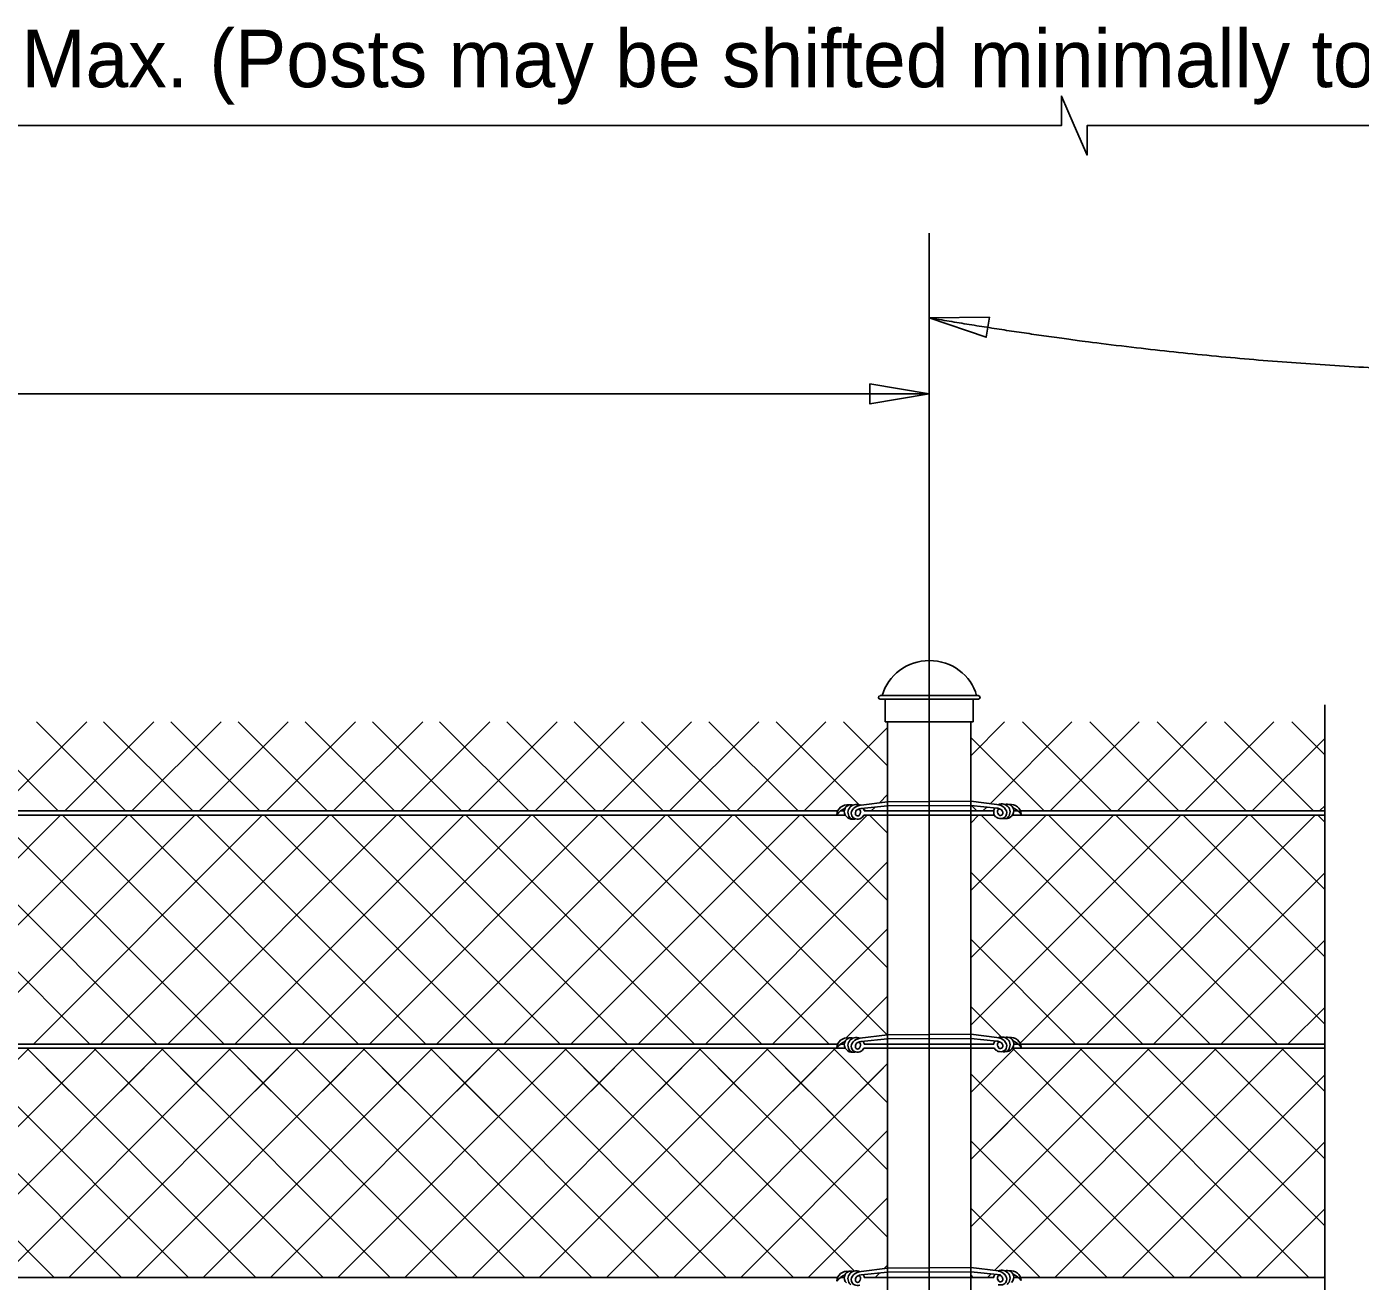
# Model space of a CAD drawing. Extents: x 0 to 41, y -96 to 25.
# Drawn here: x 12.158 to 16.836, y 20.556 to 24.956 of the extents above; entities that cross this region are included whole.
import ezdxf

# ---------------------------------------------------------------- set-up
doc = ezdxf.new("R2010")
doc.units = 0
for name, color, linetype in [('CL_Major', 7, 'Continuous'), ('Dimension', 7, 'Continuous'), ('Miscellaneous', 7, 'Continuous'), ('SteelMisc', 7, 'Continuous'), ('SteelMisc_h', 7, 'Continuous'), ('TextStructures', 7, 'Continuous')]:
    doc.layers.add(name, color=color, linetype=linetype)

msp = doc.modelspace()

# ---------------------------------------------------------------- linework, layer by layer
at = {"layer": 'CL_Major'}
msp.add_line((15.3237, 24.2317), (15.3237, 12.9956), dxfattribs=at)
at = {"layer": 'Dimension'}
for p, q in [((0.9439, 24.6092), (14.3237, 24.6092)), ((5.3237, 23.6682), (15.3237, 23.6682))]:
    msp.add_line(p, q, dxfattribs=at)
for points in [[(14.3237, 24.6092), (15.7874, 24.6092), (15.7874, 24.7126), (15.8324, 24.6092), (15.8774, 24.5059), (15.8774, 24.6092), (29.1682, 24.6092)], [(16.7107, 22.5773), (16.7107, 19.3509), (16.814, 19.3509), (16.7107, 19.3059), (16.6074, 19.2609), (16.7107, 19.2609), (16.7107, 18.3673)]]:
    msp.add_lwpolyline(points, dxfattribs=at)
for points in [[(15.3237, 23.9351), (15.5237, 23.8671), (15.5349, 23.9368)], [(15.3237, 23.6682), (15.1155, 23.7035), (15.1155, 23.6329)]]:
    msp.add_lwpolyline(points, close=True, dxfattribs=at)
msp.add_open_spline([(19.3053, 23.7363), (18.502, 23.7363), (17.1126, 23.7363), (15.9312, 23.8309), (15.3237, 23.935)], degree=2, dxfattribs=at)
at = {"layer": 'Miscellaneous'}
for p, q in [((11.9568, 22.5181), (12.2693, 22.2055)), ((12.0562, 22.2055), (12.3688, 22.5181)), ((12.1925, 22.5181), (12.505, 22.2055)), ((12.2919, 22.2055), (12.6045, 22.5181)), ((12.4282, 22.5181), (12.7407, 22.2055)), ((12.5276, 22.2055), (12.8402, 22.5181)), ((12.6639, 22.5181), (12.9765, 22.2055)), ((12.7634, 22.2055), (13.0759, 22.5181)), ((12.8996, 22.5181), (13.2122, 22.2055)), ((12.9991, 22.2055), (13.3116, 22.5181)), ((13.1353, 22.5181), (13.4479, 22.2055)), ((13.2348, 22.2055), (13.5473, 22.5181)), ((13.371, 22.5181), (13.6836, 22.2055)), ((13.4705, 22.2055), (13.783, 22.5181)), ((13.6067, 22.5181), (13.9193, 22.2055)), ((13.7062, 22.2055), (14.0187, 22.5181)), ((13.8424, 22.5181), (14.155, 22.2055)), ((13.9419, 22.2055), (14.2544, 22.5181)), ((14.0786, 22.5181), (14.3911, 22.2055)), ((14.1776, 22.2055), (14.4901, 22.5181)), ((14.3148, 22.5181), (14.6273, 22.2055)), ((14.4133, 22.2055), (14.7258, 22.5181)), ((14.5509, 22.5181), (14.8635, 22.2055)), ((14.649, 22.2055), (14.9615, 22.5181)), ((14.7871, 22.5181), (15.0782, 22.227)), ((14.8847, 22.2055), (15.1779, 22.4988)), ((15.0233, 22.5181), (15.1779, 22.3635)), ((15.4696, 22.3994), (15.5882, 22.5181)), ((15.5376, 22.2312), (15.8244, 22.5181)), ((15.651, 22.5181), (15.9635, 22.2055)), ((15.748, 22.2055), (16.0606, 22.5181)), ((15.8871, 22.5181), (16.1997, 22.2055)), ((15.9842, 22.2055), (16.2967, 22.5181)), ((16.1233, 22.5181), (16.4358, 22.2055)), ((16.2204, 22.2055), (16.5329, 22.5181)), ((16.3595, 22.5181), (16.672, 22.2055)), ((16.5957, 22.5181), (16.7107, 22.403)), ((15.4696, 22.4633), (15.7273, 22.2055)), ((16.4566, 22.2055), (16.7107, 22.4597)), ((15.1204, 22.2055), (15.1339, 22.2191)), ((15.1494, 22.2346), (15.1779, 22.2631)), ((15.4717, 22.225), (15.4911, 22.2055)), ((15.5119, 22.2055), (15.5257, 22.2194)), ((16.6923, 22.2055), (16.7107, 22.224)), ((11.4745, 21.3881), (12.2772, 22.1908)), ((11.577, 22.1908), (12.3796, 21.3881)), ((11.7103, 21.3881), (12.5129, 22.1908)), ((11.8127, 22.1908), (12.6153, 21.3881)), ((11.946, 21.3881), (12.7486, 22.1908)), ((12.0484, 22.1908), (12.851, 21.3881)), ((12.1817, 21.3881), (12.9843, 22.1908)), ((12.2841, 22.1908), (13.0867, 21.3881)), ((12.4174, 21.3881), (13.22, 22.1908)), ((12.5198, 22.1908), (13.3224, 21.3881)), ((12.6531, 21.3881), (13.4557, 22.1908)), ((12.7555, 22.1908), (13.5581, 21.3881)), ((12.8888, 21.3881), (13.6914, 22.1908)), ((12.9912, 22.1908), (13.7938, 21.3881)), ((13.1245, 21.3881), (13.9271, 22.1908)), ((13.2269, 22.1908), (14.0296, 21.3881)), ((13.3602, 21.3881), (14.1628, 22.1908)), ((13.4626, 22.1908), (14.2653, 21.3881)), ((13.5959, 21.3881), (14.3985, 22.1908)), ((13.6983, 22.1908), (14.501, 21.3881)), ((13.8316, 21.3881), (14.6342, 22.1908)), ((13.934, 22.1908), (14.7367, 21.3881)), ((14.0673, 21.3881), (14.8699, 22.1908)), ((14.1697, 22.1908), (14.9724, 21.3881)), ((14.303, 21.3881), (15.1056, 22.1908)), ((14.4059, 22.1908), (15.1762, 21.4205)), ((14.6421, 22.1908), (15.1779, 21.6549)), ((14.8782, 22.1908), (15.1779, 21.8911)), ((15.0931, 22.2121), (15.0997, 22.2055)), ((15.1144, 22.1908), (15.1779, 22.1273)), ((15.4696, 21.4547), (16.2056, 22.1908)), ((15.4696, 21.6909), (15.9695, 22.1908)), ((15.4696, 21.9271), (15.7333, 22.1908)), ((15.4696, 22.1633), (15.4971, 22.1908)), ((15.5059, 22.1908), (16.3085, 21.3881)), ((15.6425, 21.3915), (16.4418, 22.1908)), ((15.7421, 22.1908), (16.5447, 21.3881)), ((15.8749, 21.3881), (16.6775, 22.1908)), ((15.9782, 22.1908), (16.7107, 21.4583)), ((16.2144, 22.1908), (16.7107, 21.6945)), ((16.4506, 22.1908), (16.7107, 21.9307)), ((16.6868, 22.1908), (16.7107, 22.1669)), ((14.5387, 21.3881), (15.1779, 22.0274)), ((15.4696, 21.9914), (16.0728, 21.3881)), ((16.1106, 21.3881), (16.7107, 21.9883)), ((14.7744, 21.3881), (15.1779, 21.7917)), ((15.4696, 21.7557), (15.8371, 21.3881)), ((16.3463, 21.3881), (16.7107, 21.7526)), ((15.0311, 21.4092), (15.1779, 21.556)), ((15.4696, 21.52), (15.5766, 21.413)), ((16.582, 21.3881), (16.7107, 21.5169)), ((11.3635, 20.57), (12.1669, 21.3734)), ((11.4516, 21.3734), (12.255, 20.57)), ((11.5992, 20.57), (12.4026, 21.3734)), ((11.6873, 21.3734), (12.4907, 20.57)), ((11.8349, 20.57), (12.6383, 21.3734)), ((11.923, 21.3734), (12.7264, 20.57)), ((12.0706, 20.57), (12.874, 21.3734)), ((12.1587, 21.3734), (12.9621, 20.57)), ((12.3063, 20.57), (13.1097, 21.3734)), ((12.3944, 21.3734), (13.1978, 20.57)), ((12.542, 20.57), (13.3454, 21.3734)), ((12.6301, 21.3734), (13.4335, 20.57)), ((12.7777, 20.57), (13.5811, 21.3734)), ((12.8658, 21.3734), (13.6692, 20.57)), ((13.0134, 20.57), (13.8168, 21.3734)), ((13.1015, 21.3734), (13.9049, 20.57)), ((13.2491, 20.57), (14.0525, 21.3734)), ((13.3372, 21.3734), (14.1406, 20.57)), ((13.4848, 20.57), (14.2882, 21.3734)), ((13.5729, 21.3734), (14.3763, 20.57)), ((13.7205, 20.57), (14.5239, 21.3734)), ((13.8086, 21.3734), (14.612, 20.57)), ((13.9562, 20.57), (14.7596, 21.3734)), ((14.0443, 21.3734), (14.8477, 20.57)), ((14.1919, 20.57), (14.9953, 21.3734)), ((14.28, 21.3734), (15.0612, 20.5922)), ((14.5157, 21.3734), (15.1779, 20.7112)), ((14.7514, 21.3734), (15.1779, 20.9469)), ((14.9871, 21.3734), (15.1779, 21.1826)), ((15.4696, 21.2186), (15.6244, 21.3734)), ((15.4696, 20.7472), (16.0958, 21.3734)), ((15.4696, 20.9829), (15.8601, 21.3734)), ((15.5526, 20.5944), (16.3315, 21.3734)), ((15.6162, 21.3734), (16.4196, 20.57)), ((15.7638, 20.57), (16.5672, 21.3734)), ((15.8519, 21.3734), (16.6553, 20.57)), ((16.0876, 21.3734), (16.7107, 20.7503)), ((16.3233, 21.3734), (16.7107, 20.986)), ((16.5595, 21.3734), (16.7107, 21.2222)), ((12.1677, 21.1385), (12.3344, 21.3051)), ((12.2269, 21.3051), (12.3936, 21.1385)), ((12.4034, 21.1385), (12.5701, 21.3051)), ((12.4626, 21.3051), (12.6293, 21.1385)), ((12.6391, 21.1385), (12.8058, 21.3051)), ((12.6983, 21.3051), (12.865, 21.1385)), ((12.8748, 21.1385), (13.0415, 21.3051)), ((12.934, 21.3051), (13.1007, 21.1385)), ((13.1105, 21.1385), (13.2772, 21.3051)), ((13.1697, 21.3051), (13.3364, 21.1385)), ((13.3462, 21.1385), (13.5129, 21.3051)), ((13.4054, 21.3051), (13.5721, 21.1385)), ((13.5819, 21.1385), (13.7486, 21.3051)), ((13.6411, 21.3051), (13.8078, 21.1385)), ((13.8176, 21.1385), (13.9843, 21.3051)), ((13.8768, 21.3051), (14.0435, 21.1385)), ((14.0533, 21.1385), (14.22, 21.3051)), ((14.1125, 21.3051), (14.2792, 21.1385)), ((14.289, 21.1385), (14.4557, 21.3051)), ((14.3482, 21.3051), (14.5149, 21.1385)), ((14.4276, 20.57), (15.1779, 21.3203)), ((14.5247, 21.1385), (14.6914, 21.3051)), ((14.5839, 21.3051), (14.7506, 21.1385)), ((14.7604, 21.1385), (14.9271, 21.3051)), ((14.8196, 21.3051), (14.9863, 21.1385)), ((14.9961, 21.1385), (15.1628, 21.3051)), ((15.4696, 21.2843), (16.1839, 20.57)), ((16, 20.57), (16.7107, 21.2807)), ((15.4696, 20.9829), (15.5991, 21.1123)), ((14.6633, 20.57), (15.1779, 21.0846)), ((15.4696, 21.0486), (15.9482, 20.57)), ((16.2352, 20.57), (16.7107, 21.0454)), ((14.899, 20.57), (15.1779, 20.8489)), ((15.4696, 20.8129), (15.7125, 20.57)), ((16.4709, 20.57), (16.7107, 20.8097)), ((15.1347, 20.57), (15.1499, 20.5851)), ((15.1658, 20.601), (15.1779, 20.6132)), ((15.5281, 20.57), (15.5406, 20.5824)), ((15.4696, 20.5772), (15.4768, 20.57)), ((16.7066, 20.57), (16.7107, 20.574))]:
    msp.add_line(p, q, dxfattribs=at)
at = {"layer": 'SteelMisc'}
for p, q in [((15.1514, 22.6101), (15.496, 22.6101)), ((15.496, 22.5978), (15.1514, 22.5978)), ((15.1697, 22.5181), (15.1697, 22.5978)), ((15.4778, 22.5181), (15.4778, 22.5978)), ((15.4778, 22.5181), (15.1697, 22.5181)), ((15.1779, 16.0337), (15.1779, 22.5181)), ((15.4696, 16.0337), (15.4696, 22.5181)), ((15.1779, 22.2381), (15.0851, 22.2265)), ((15.1779, 22.2236), (15.0851, 22.214)), ((15.1779, 22.2381), (15.4691, 22.2398)), ((15.1779, 22.2236), (15.4691, 22.2253)), ((15.4691, 22.2398), (15.561, 22.2283)), ((15.4691, 22.2253), (15.561, 22.2158)), ((5.6284, 22.2055), (15.0028, 22.2055)), ((5.6317, 22.1908), (15.0294, 22.1908)), ((15.0127, 22.2055), (15.0259, 22.2055)), ((15.0943, 22.1908), (15.1779, 22.1908)), ((15.0958, 22.2055), (15.1779, 22.2055)), ((15.4696, 22.2055), (15.55, 22.2055)), ((15.4696, 22.1908), (15.5527, 22.1908)), ((15.6154, 22.1908), (16.7107, 22.1908)), ((15.6204, 22.2055), (15.6356, 22.2055)), ((15.6441, 22.2055), (16.7107, 22.2055)), ((5.6284, 21.3881), (15.0028, 21.3881)), ((15.0127, 21.3881), (15.0259, 21.3881)), ((15.1779, 21.4207), (15.0808, 21.4086)), ((15.1779, 21.4062), (15.0851, 21.3966)), ((15.0958, 21.3881), (15.1779, 21.3881)), ((15.1779, 21.4207), (15.4691, 21.4224)), ((15.1779, 21.4062), (15.4691, 21.4079)), ((15.4691, 21.4224), (15.561, 21.4109)), ((15.4691, 21.4079), (15.561, 21.3984)), ((15.4696, 21.3881), (15.55, 21.3881)), ((15.6204, 21.3881), (15.6356, 21.3881)), ((15.6441, 21.3881), (16.7107, 21.3881)), ((5.6317, 21.3734), (15.0294, 21.3734)), ((15.0943, 21.3734), (15.1779, 21.3734)), ((15.4696, 21.3734), (15.5527, 21.3734)), ((15.6154, 21.3734), (16.7107, 21.3734)), ((15.1779, 20.6026), (15.0851, 20.5909)), ((15.1779, 20.5881), (15.0851, 20.5784)), ((15.1779, 20.6026), (15.4691, 20.6043)), ((15.1779, 20.5881), (15.4691, 20.5897)), ((15.4691, 20.6043), (15.5668, 20.5927)), ((15.4691, 20.5897), (15.5738, 20.5791)), ((5.6284, 20.57), (15.0028, 20.57)), ((15.0127, 20.57), (15.0259, 20.57)), ((15.0958, 20.57), (15.1779, 20.57)), ((15.4696, 20.57), (15.55, 20.57)), ((15.6204, 20.57), (15.6356, 20.57)), ((15.6441, 20.57), (16.7107, 20.57))]:
    msp.add_line(p, q, dxfattribs=at)
for centre, start, end in [((15.1516, 22.6038), 91.1647, 268.8353), ((15.4959, 22.6038), 271.1647, 88.8353)]:
    msp.add_arc(centre, 0.00613, start, end, dxfattribs=at)
for centre, major_axis, ratio, start_param, end_param in [((15.3244, 22.569), (0.1711, 0), 0.957868, 0.252602, 2.888574), ((15.037, 22.1913), (0.0373, 0), 0.957868, 1.427863, 3.108042), ((15.0495, 22.2057), (0.023, 0), 0.957868, 1.234085, 2.861055), ((15.0683, 22.2004), (0.0295, 0), 0.957868, 1.132635, 3.996184), ((15.0817, 22.2022), (-0.0303, -0.0108), 0.724765, 4.35367, 6.224248), ((15.5644, 22.2039), (0.0303, -0.0108), 0.724765, 0.058937, 1.929515), ((15.5778, 22.2021), (-0.0295, 0), 0.957868, 2.287002, 5.15055), ((15.5966, 22.2075), (-0.023, 0), 0.957868, 3.422131, 5.0491), ((15.6091, 22.193), (-0.0373, 0), 0.957868, 3.175144, 4.855322), ((15.0581, 22.1516), (-0.0724, 0), 0.957868, 5.133134, 5.652106), ((15.0507, 22.2032), (-0.0249, 0), 0.957868, 5.913851, 7.104804), ((15.052, 22.1992), (0.0231, 0), 0.957868, 3.795406, 4.839145), ((15.0581, 22.1935), (0.0206, -0.0021), 0.798607, 4.32653, 5.170153), ((15.0716, 22.1935), (0.0206, -0.0021), 0.798607, 3.319436, 5.220153), ((15.0784, 22.1981), (-0.0139, 0), 0.957868, 5.075258, 6.485782), ((15.0728, 22.1957), (-0.00795, 0), 0.957868, 0.039428, 2.999692), ((15.0868, 22.1892), (-0.0259, 0), 0.957868, 4.777514, 5.251802), ((15.0711, 22.2015), (0.0119, 0), 0.957868, 5.725876, 7.416677), ((15.0642, 22.2123), (0.0391, 0), 0.957868, 5.134108, 5.41974), ((15.0711, 22.2015), (0.0119, 0), 0.957868, 5.639684, 5.725876), ((15.0713, 22.2003), (0.0251, 0), 0.957868, 5.531357, 5.877802), ((15.0713, 22.2003), (0.0251, 0), 0.957868, 0.221743, 0.642584), ((15.5748, 22.202), (-0.0251, 0), 0.957868, 6.136824, 7.035014), ((15.5748, 22.202), (-0.0251, 0), 0.957868, 5.640694, 6.136824), ((15.5819, 22.2141), (-0.0391, 0), 0.957868, 0.863445, 1.149078), ((15.5593, 22.191), (0.0259, 0), 0.957868, 1.031384, 1.505671), ((15.575, 22.2033), (-0.0119, 0), 0.957868, 5.149694, 6.840495), ((15.575, 22.2033), (-0.0119, 0), 0.957868, 0.560069, 0.643501), ((15.5734, 22.1975), (0.00795, 0), 0.957868, 3.283494, 6.243757), ((15.5745, 22.1953), (-0.0206, -0.0021), 0.798607, 1.063032, 2.96375), ((15.5677, 22.1999), (0.0139, 0), 0.957868, 6.080589, 7.491112), ((15.588, 22.1953), (-0.0206, -0.0021), 0.798607, 1.113032, 1.956656), ((15.5941, 22.201), (-0.0231, 0), 0.957868, 1.44404, 2.487779), ((15.5955, 22.205), (0.0249, 0), 0.957868, 5.461566, 6.65252), ((15.588, 22.1533), (0.0724, 0), 0.957868, 0.631079, 1.150052), ((15.037, 21.3739), (0.0373, 0), 0.957868, 1.427863, 3.108042), ((15.0581, 21.3342), (-0.0724, 0), 0.957868, 5.133134, 5.652106), ((15.0507, 21.3858), (-0.0249, 0), 0.957868, 5.913851, 7.089857), ((15.0495, 21.3883), (0.023, 0), 0.957868, 1.234085, 2.861055), ((15.0683, 21.383), (0.0295, 0), 0.957868, 1.132635, 3.996184), ((15.0817, 21.3848), (-0.0303, -0.0108), 0.724765, 4.490702, 6.224248), ((15.0784, 21.3807), (-0.0139, 0), 0.957868, 5.075258, 6.485782), ((15.0728, 21.3783), (-0.00795, 0), 0.957868, 0.039428, 2.999692), ((15.0868, 21.3718), (-0.0259, 0), 0.957868, 4.777514, 5.251802), ((15.0711, 21.3841), (0.0119, 0), 0.957868, 5.725876, 7.416677), ((15.0711, 21.3841), (0.0119, 0), 0.957868, 5.639684, 5.725876), ((15.0713, 21.3829), (0.0251, 0), 0.957868, 0.221743, 0.642584), ((15.5748, 21.3846), (-0.0251, 0), 0.957868, 5.640694, 6.136824), ((15.5644, 21.3865), (0.0303, -0.0108), 0.724765, 0.058937, 1.929515), ((15.5593, 21.3736), (0.0259, 0), 0.957868, 1.031384, 1.505671), ((15.575, 21.3859), (-0.0119, 0), 0.957868, 5.149694, 6.840495), ((15.575, 21.3859), (-0.0119, 0), 0.957868, 0.560069, 0.643501), ((15.5778, 21.3847), (-0.0295, 0), 0.957868, 2.287002, 5.15055), ((15.5734, 21.3801), (0.00795, 0), 0.957868, 3.283494, 6.243757), ((15.5745, 21.3779), (-0.0206, -0.0021), 0.798607, 1.063032, 2.96375), ((15.5677, 21.3825), (0.0139, 0), 0.957868, 6.080589, 7.491112), ((15.5966, 21.3901), (-0.023, 0), 0.957868, 3.422131, 5.0491), ((15.6091, 21.3756), (-0.0373, 0), 0.957868, 3.175144, 4.855322), ((15.5955, 21.3876), (0.0249, 0), 0.957868, 5.476514, 6.65252), ((15.588, 21.3359), (0.0724, 0), 0.957868, 0.631079, 1.150052), ((15.052, 21.3818), (0.0231, 0), 0.957868, 3.779554, 4.839145), ((15.0581, 21.3761), (0.0206, -0.0021), 0.798607, 4.32653, 5.170153), ((15.0716, 21.3761), (0.0206, -0.0021), 0.798607, 3.319436, 5.220153), ((15.0642, 21.3949), (0.0391, 0), 0.957868, 5.134108, 5.41974), ((15.0713, 21.3829), (0.0251, 0), 0.957868, 5.531357, 5.877802), ((15.5748, 21.3846), (-0.0251, 0), 0.957868, 0.487549, 0.751829), ((15.5819, 21.3967), (-0.0391, 0), 0.957868, 0.863445, 1.149078), ((15.588, 21.3779), (-0.0206, -0.0021), 0.798607, 1.113032, 1.956656), ((15.5941, 21.3836), (-0.0231, 0), 0.957868, 1.44404, 2.503632), ((15.037, 20.5557), (0.0373, 0), 0.957868, 1.427863, 3.108042), ((15.0495, 20.5702), (0.023, 0), 0.957868, 1.234085, 2.861055), ((15.0683, 20.5648), (0.0295, 0), 0.957868, 1.132635, 3.996184), ((15.0817, 20.5666), (-0.0303, -0.0108), 0.724765, 4.35367, 6.224248), ((15.5748, 20.5665), (-0.0251, 0), 0.957868, 5.633507, 6.136824), ((15.5778, 20.5666), (-0.0295, 0), 0.957868, 2.287002, 5.15055), ((15.5644, 20.5684), (0.0303, -0.0108), 0.724765, 0.058937, 1.792483), ((15.5966, 20.5719), (-0.023, 0), 0.957868, 3.422131, 5.0491), ((15.6091, 20.5575), (-0.0373, 0), 0.957868, 3.175144, 4.855322), ((15.588, 20.5178), (0.0724, 0), 0.957868, 0.631079, 1.150052), ((15.0581, 20.516), (-0.0724, 0), 0.957868, 5.133134, 5.652106), ((15.0507, 20.5677), (-0.0249, 0), 0.957868, 5.913851, 7.104804), ((15.0716, 20.558), (0.0206, -0.0021), 0.798607, 3.319436, 5.220153), ((15.0784, 20.5625), (-0.0139, 0), 0.957868, 5.822914, 6.485782), ((15.0728, 20.5601), (-0.00795, 0), 0.957868, 0.039428, 2.999692), ((15.0868, 20.5537), (-0.0259, 0), 0.957868, 4.777514, 5.646371), ((15.0711, 20.5659), (0.0119, 0), 0.957868, 5.725876, 7.416677), ((15.0711, 20.5659), (0.0119, 0), 0.957868, 5.639684, 5.725876), ((15.0713, 20.5647), (0.0251, 0), 0.957868, 0.221743, 0.642584), ((15.575, 20.5677), (-0.0119, 0), 0.957868, 4.818879, 6.840495), ((15.575, 20.5677), (-0.0119, 0), 0.957868, 0.560069, 0.643501), ((15.5734, 20.5619), (0.00795, 0), 0.957868, 3.283494, 6.243757), ((15.5745, 20.5597), (-0.0206, -0.0021), 0.798607, 1.063032, 2.96375), ((15.5677, 20.5643), (0.0139, 0), 0.957868, 6.080589, 7.760381), ((15.5955, 20.5694), (0.0249, 0), 0.957868, 5.476514, 6.65252)]:
    msp.add_ellipse(centre, major_axis=major_axis, ratio=ratio, start_param=start_param, end_param=end_param, dxfattribs=at)
at = {"layer": 'SteelMisc_h'}
for p, q in [((15.1779, 22.2055), (15.4696, 22.2055)), ((15.1779, 22.1908), (15.4696, 22.1908)), ((15.1779, 21.3881), (15.4696, 21.3881)), ((15.1779, 21.3734), (15.4696, 21.3734)), ((15.1779, 20.57), (15.4696, 20.57))]:
    msp.add_line(p, q, dxfattribs=at)

# ---------------------------------------------------------------- texts
at = {"layer": 'TextStructures'}
msp.add_text('Equal Spaces @ 10\'-0" Max. (Posts may be shifted minimally to meet required clearances)', height=0.2016, dxfattribs=at).set_placement((9.2913, 24.7438))

doc.saveas('drawing.dxf')
